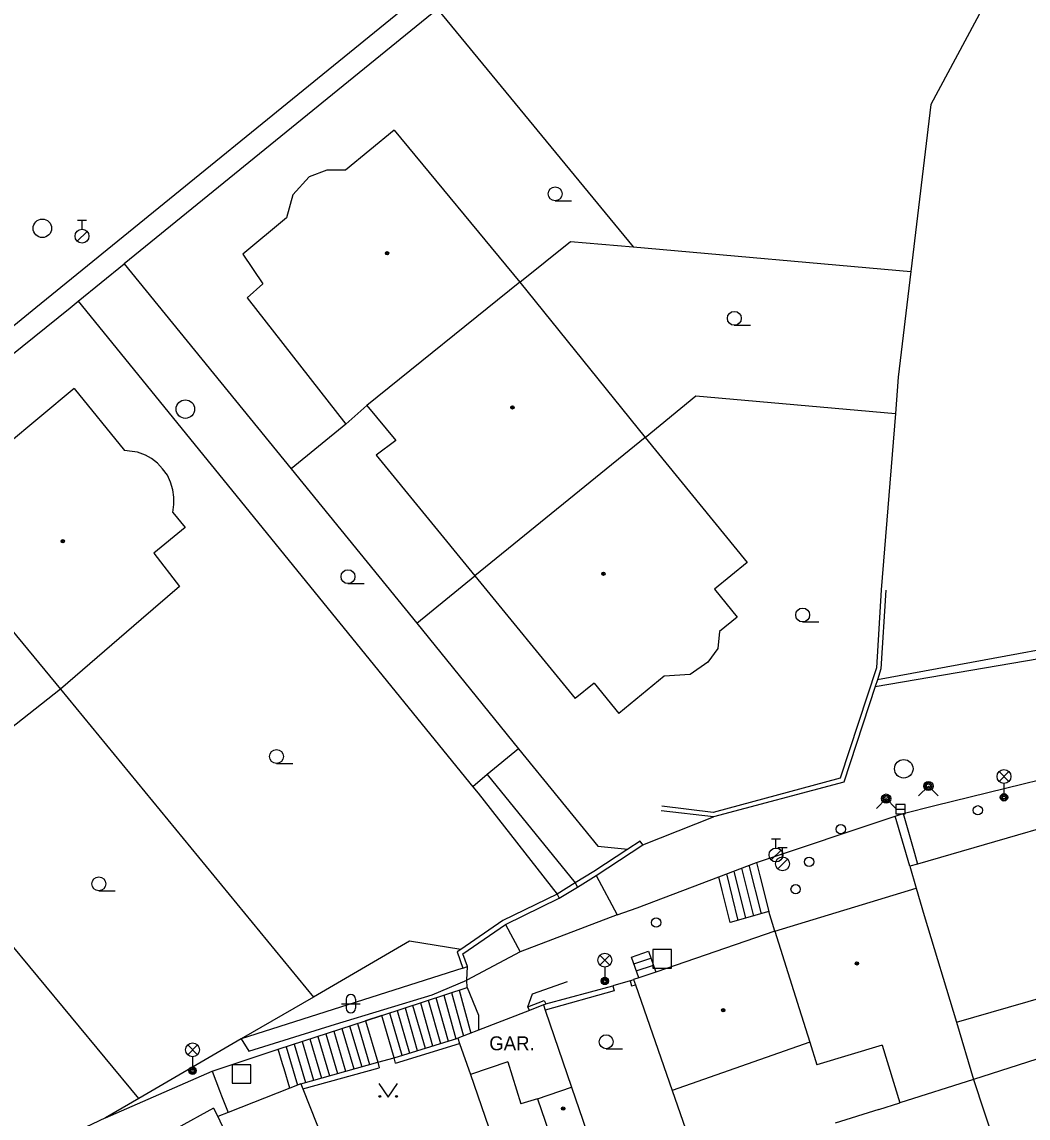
# Model space of a CAD drawing. Extents: x -598233 to -596890, y -1157848 to -1156431.
# Drawn here: x -597251.6 to -597197.2, y -1157432.7 to -1157373.5 of the extents above; entities that cross this region are included whole.
import ezdxf

# ---------------------------------------------------------------- set-up
doc = ezdxf.new("R2010")
doc.units = 0
for name, color, linetype in [('Level 10', 7, 'Continuous'), ('Level 11', 7, 'Continuous'), ('Level 26', 7, 'Continuous'), ('Level 27', 7, 'Continuous'), ('Level 28', 7, 'Continuous'), ('Level 31', 7, 'Continuous'), ('Level 33', 7, 'Continuous'), ('Level 36', 7, 'Continuous'), ('Level 39', 7, 'Continuous'), ('Level 41', 7, 'Continuous'), ('Level 5', 7, 'Continuous'), ('Level 7', 7, 'Continuous'), ('Level 8', 7, 'Continuous'), ('Level 9', 7, 'Continuous')]:
    doc.layers.add(name, color=color, linetype=linetype)

msp = doc.modelspace()

# ---------------------------------------------------------------- linework, layer by layer
at = {"layer": 'Level 10'}
for points in [[(-597250.82, -1157388.95), (-597229.74, -1157371.81)], [(-597253.2199, -1157390.9), (-597250.82, -1157388.95)], [(-597205.5, -1157409.4), (-597174.4099, -1157404.1), (-597163.67, -1157401.73), (-597154.26, -1157399.59), (-597141.84, -1157396.29)], [(-597204, -1157416.26), (-597202.29, -1157415.83), (-597191.86, -1157413.27)], [(-597211.9099, -1157418.9), (-597204.43, -1157416.4)], [(-597213.95, -1157419.68), (-597211.9099, -1157418.9)], [(-597220.57, -1157419.61), (-597219.44, -1157421.74)], [(-597219.44, -1157421.74), (-597218.35, -1157421.36), (-597213.95, -1157419.68)]]:
    msp.add_lwpolyline(points, dxfattribs=at)
at = {"layer": 'Level 11'}
for points in [[(-597229.14, -1157372.85), (-597246.05, -1157386.6)], [(-597229.14, -1157372.85), (-597218.57, -1157385.69)], [(-597224.69, -1157387.59), (-597221.95, -1157385.39), (-597218.57, -1157385.69)], [(-597218.57, -1157385.69), (-597203.57, -1157387.01)], [(-597248.53, -1157388.62), (-597246.05, -1157386.6)], [(-597246.05, -1157386.6), (-597237.04, -1157397.6599)], [(-597256.03, -1157394.64), (-597248.97, -1157388.97), (-597248.53, -1157388.62)], [(-597248.53, -1157388.62), (-597227.22, -1157414.82), (-597226.94, -1157415.17)], [(-597217.92, -1157395.9699), (-597215.18, -1157393.73), (-597204.4, -1157394.67)], [(-597234.09, -1157395.25), (-597237.04, -1157397.6599)], [(-597237.04, -1157397.6599), (-597230.26, -1157406)], [(-597230.26, -1157406), (-597227.12, -1157403.44)], [(-597230.26, -1157406), (-597224.76, -1157412.77), (-597220.48, -1157418.03), (-597218.86, -1157418.19)], [(-597249.5, -1157409.56), (-597235.83, -1157426.17)], [(-597224.76, -1157412.77), (-597226.45, -1157414.16), (-597227.22, -1157414.82)], [(-597226.45, -1157414.16), (-597221.7, -1157420.01), (-597221.57, -1157420.23)], [(-597226.94, -1157415.17), (-597222.68, -1157420.61)], [(-597245.26, -1157431.64), (-597258.01, -1157416.28)], [(-597204.43, -1157416.4), (-597204, -1157416.26)], [(-597203.64, -1157419.11), (-597204.43, -1157416.4)], [(-597204, -1157416.26), (-597203.38, -1157418.4), (-597203.21, -1157418.99)], [(-597213.13, -1157419.37), (-597212.5, -1157421.9099)], [(-597212.73, -1157419.21), (-597212.08, -1157421.8)], [(-597212.32, -1157419.06), (-597211.6599, -1157421.68)], [(-597211.9099, -1157418.9), (-597211.73, -1157419.62), (-597211.24, -1157421.56)], [(-597211.24, -1157421.56), (-597213.34, -1157422.15), (-597213.76, -1157420.42), (-597213.95, -1157419.68)], [(-597213.54, -1157419.52), (-597212.92, -1157422.03)], [(-597222.68, -1157420.61), (-597222.56, -1157420.83)], [(-597210.92, -1157422.61), (-597203.29, -1157420.3)], [(-597219.44, -1157421.74), (-597224.68, -1157423.73)], [(-597210.92, -1157422.61), (-597211.24, -1157421.56)], [(-597225.4699, -1157422.26), (-597224.68, -1157423.73)], [(-597224.68, -1157423.73), (-597227.56, -1157425.25)], [(-597218.27, -1157425.13), (-597218.6599, -1157424.01), (-597217.74, -1157423.69), (-597217.35, -1157424.82)], [(-597218.53, -1157424.38), (-597217.61, -1157424.07)], [(-597227.76, -1157424.61), (-597239.73, -1157428.43)], [(-597227.56, -1157425.25), (-597227.52, -1157424.52)], [(-597218.4, -1157424.76), (-597217.48, -1157424.44)], [(-597234.64, -1157427.64), (-597229.43, -1157426.04), (-597227.56, -1157425.25)], [(-597227.54, -1157425.65), (-597227.56, -1157425.25)], [(-597224.25, -1157426.69), (-597224, -1157425.99), (-597222.12, -1157425.33)], [(-597232.15, -1157427.1599), (-597227.54, -1157425.65)], [(-597228.38, -1157425.92), (-597227.74, -1157428.28)], [(-597227.96, -1157425.79), (-597227.33, -1157428.12)], [(-597227.54, -1157425.65), (-597226.93, -1157427.15), (-597226.92, -1157427.96)], [(-597230.06, -1157426.48), (-597229.4, -1157428.81)], [(-597229.64, -1157426.34), (-597228.98, -1157428.68)], [(-597229.2199, -1157426.2), (-597228.56, -1157428.55)], [(-597228.8, -1157426.06), (-597228.15, -1157428.43)], [(-597224.25, -1157426.69), (-597223.37, -1157426.35), (-597223.29, -1157426.54)], [(-597231.73, -1157427.02), (-597231.06, -1157429.31)], [(-597231.31, -1157426.89), (-597230.65, -1157429.19)], [(-597230.89, -1157426.75), (-597230.23, -1157429.06)], [(-597230.48, -1157426.61), (-597229.81, -1157428.93)], [(-597224.17, -1157426.89), (-597224.25, -1157426.69)], [(-597239.73, -1157428.43), (-597239.32, -1157429.08), (-597234.64, -1157427.64)], [(-597237.73, -1157428.99), (-597233.02, -1157427.45)], [(-597233.88, -1157427.73), (-597233.23, -1157429.93)], [(-597233.45, -1157427.59), (-597232.8, -1157429.81)], [(-597233.02, -1157427.45), (-597232.15, -1157427.1599)], [(-597233.02, -1157427.45), (-597232.36, -1157429.69)], [(-597231.48, -1157429.44), (-597232.15, -1157427.1599)], [(-597235.59, -1157428.29), (-597234.96, -1157430.42)], [(-597235.1599, -1157428.15), (-597234.53, -1157430.3)], [(-597234.73, -1157428.01), (-597234.1, -1157430.17)], [(-597234.3, -1157427.87), (-597233.6599, -1157430.05)], [(-597237.3, -1157428.85), (-597236.69, -1157430.92)], [(-597236.87, -1157428.71), (-597236.26, -1157430.78)], [(-597236.44, -1157428.57), (-597235.83, -1157430.6599)], [(-597236.02, -1157428.43), (-597235.4, -1157430.54)], [(-597209.04, -1157428.61), (-597216.47, -1157431.22)], [(-597241.31, -1157430.17), (-597237.73, -1157428.99)], [(-597237.11, -1157431.09), (-597237.42, -1157430.04), (-597237.5, -1157429.77), (-597237.73, -1157428.99)], [(-597232.36, -1157429.69), (-597231.48, -1157429.44)], [(-597196.32, -1157429.38), (-597200.19, -1157430.62)], [(-597247.06, -1157432.68), (-597241.31, -1157430.17)], [(-597241.31, -1157430.17), (-597240.9, -1157431.21), (-597240.79, -1157431.5), (-597240.44, -1157432.39)], [(-597227.36, -1157430.34), (-597226.38, -1157433.18)], [(-597200.19, -1157430.62), (-597198.51, -1157435.75)], [(-597223.73, -1157431.66), (-597221.9, -1157431.03)], [(-597216.47, -1157431.22), (-597215.05, -1157435.3)], [(-597205.3, -1157432.23), (-597204.17, -1157431.87)], [(-597205.3, -1157432.23), (-597207.67, -1157432.98)]]:
    msp.add_lwpolyline(points, dxfattribs=at)
at = {"layer": 'Level 26'}
for points in [[(-597217.51, -1157424.61), (-597216.51, -1157424.61), (-597216.51, -1157423.61), (-597217.51, -1157423.61)], [(-597240.2199, -1157430.82), (-597239.2199, -1157430.82), (-597239.2199, -1157429.82), (-597240.2199, -1157429.82)]]:
    msp.add_lwpolyline(points, close=True, dxfattribs=at)
at = {"layer": 'Level 27'}
msp.add_line((-597204.39, -1157416.03), (-597203.89, -1157416.03), dxfattribs=at)
msp.add_lwpolyline([(-597204.39, -1157416.28), (-597203.89, -1157416.28), (-597203.89, -1157415.78), (-597204.39, -1157415.78)], close=True, dxfattribs=at)
for centre in [(-597250.4699, -1157384.68), (-597242.75, -1157394.44), (-597203.96, -1157413.85)]:
    msp.add_circle(centre, 0.5, dxfattribs=at)
at = {"layer": 'Level 28'}
for p, q in [((-597248.58, -1157384.235), (-597248.08, -1157384.235)), ((-597248.33, -1157384.735), (-597248.33, -1157384.235)), ((-597248.588, -1157385.382), (-597248.058, -1157384.852)), ((-597211.11, -1157417.625), (-597210.61, -1157417.625)), ((-597210.86, -1157418.125), (-597210.86, -1157417.625)), ((-597211.118, -1157418.772), (-597210.588, -1157418.242)), ((-597210.76, -1157418.105), (-597210.26, -1157418.105)), ((-597210.51, -1157418.605), (-597210.51, -1157418.105)), ((-597210.768, -1157419.252), (-597210.238, -1157418.722))]:
    msp.add_line(p, q, dxfattribs=at)
for centre, radius in [((-597248.33, -1157385.11), 0.375), ((-597199.96, -1157416.09), 0.25), ((-597210.86, -1157418.5), 0.375), ((-597210.51, -1157418.98), 0.375), ((-597209.07, -1157418.87), 0.25), ((-597209.8, -1157420.35), 0.25), ((-597217.33, -1157422.15), 0.25)]:
    msp.add_circle(centre, radius, dxfattribs=at)
at = {"layer": 'Level 31'}
for points in [[(-597203.16, -1157415.31), (-597202.63, -1157414.78), (-597202.1, -1157415.31)], [(-597205.4399, -1157415.99), (-597204.9099, -1157415.46), (-597204.3799, -1157415.99)]]:
    msp.add_lwpolyline(points, dxfattribs=at)
for centre, radius in [((-597202.63, -1157414.78), 0.25), ((-597202.63, -1157414.78), 0.18), ((-597202.63, -1157414.78), 0.11), ((-597204.9099, -1157415.46), 0.25), ((-597204.9099, -1157415.46), 0.18), ((-597204.9099, -1157415.46), 0.11), ((-597207.36, -1157417.11), 0.25)]:
    msp.add_circle(centre, radius, dxfattribs=at)
at = {"layer": 'Level 33'}
for p, q in [((-597198.815, -1157414.53), (-597198.285, -1157414)), ((-597198.815, -1157414), (-597198.285, -1157414.53)), ((-597198.55, -1157414.64), (-597198.55, -1157415.39)), ((-597220.365, -1157424.44), (-597219.835, -1157423.91)), ((-597220.365, -1157423.91), (-597219.835, -1157424.44)), ((-597220.1, -1157424.55), (-597220.1, -1157425.3)), ((-597242.625, -1157429.28), (-597242.095, -1157428.75)), ((-597242.625, -1157428.75), (-597242.095, -1157429.28)), ((-597242.36, -1157429.39), (-597242.36, -1157430.14))]:
    msp.add_line(p, q, dxfattribs=at)
for centre, radius in [((-597198.55, -1157414.265), 0.375), ((-597198.55, -1157415.39), 0.2), ((-597198.55, -1157415.39), 0.1445), ((-597198.55, -1157415.39), 0.0876), ((-597220.1, -1157424.175), 0.375), ((-597220.1, -1157425.3), 0.2), ((-597220.1, -1157425.3), 0.1445), ((-597220.1, -1157425.3), 0.0876), ((-597242.36, -1157429.015), 0.375), ((-597242.36, -1157430.14), 0.2), ((-597242.36, -1157430.14), 0.1445), ((-597242.36, -1157430.14), 0.0876)]:
    msp.add_circle(centre, radius, dxfattribs=at)
at = {"layer": 'Level 36'}
for p, q in [((-597222.78, -1157383.195), (-597221.905, -1157383.195)), ((-597213.11, -1157389.915), (-597212.235, -1157389.915)), ((-597233.9699, -1157403.855), (-597233.0949, -1157403.855)), ((-597209.42, -1157405.925), (-597208.545, -1157405.925)), ((-597237.83, -1157413.565), (-597236.955, -1157413.565)), ((-597247.42, -1157420.435), (-597246.545, -1157420.435)), ((-597234.316, -1157426.526), (-597233.316, -1157426.526)), ((-597234.066, -1157426.276), (-597234.066, -1157426.776)), ((-597233.566, -1157426.276), (-597233.566, -1157426.776)), ((-597220.03, -1157428.955), (-597219.155, -1157428.955))]:
    msp.add_line(p, q, dxfattribs=at)
msp.add_lwpolyline([(-597232.3, -1157430.83), (-597231.8, -1157431.58), (-597231.3, -1157430.83)], dxfattribs=at)
for centre, radius in [((-597222.7801, -1157382.8199), 0.375), ((-597213.1101, -1157389.5399), 0.375), ((-597233.97, -1157403.4799), 0.375), ((-597209.4201, -1157405.5499), 0.375), ((-597237.8301, -1157413.1899), 0.375), ((-597247.4201, -1157420.0599), 0.375), ((-597220.0301, -1157428.5799), 0.375), ((-597232.2502, -1157431.5298), 0.05), ((-597231.3508, -1157431.5298), 0.05)]:
    msp.add_circle(centre, radius, dxfattribs=at)
for centre, start, end in [((-597233.8157, -1157426.2763), 0, 180), ((-597233.8157, -1157426.7763), 180, 0)]:
    msp.add_arc(centre, 0.25, start, end, dxfattribs=at)
at = {"layer": 'Level 39'}
for centre, radius in [((-597231.86, -1157386.03), 0.09), ((-597231.86, -1157386.03), 0.0398), ((-597225.09, -1157394.35), 0.09), ((-597225.09, -1157394.35), 0.0398), ((-597249.37, -1157401.57), 0.09), ((-597249.37, -1157401.57), 0.0398), ((-597220.18, -1157403.32), 0.09), ((-597220.18, -1157403.32), 0.0398), ((-597206.49, -1157424.35), 0.09), ((-597206.49, -1157424.35), 0.0398), ((-597213.71, -1157426.88), 0.09), ((-597213.71, -1157426.88), 0.0398), ((-597222.35, -1157432.19), 0.09), ((-597222.35, -1157432.19), 0.0398)]:
    msp.add_circle(centre, radius, dxfattribs=at)
at = {"layer": 'Level 5'}
for points in [[(-597231.48, -1157379.39), (-597234.11, -1157381.55)], [(-597231.48, -1157379.39), (-597224.69, -1157387.59)], [(-597235.12, -1157381.55), (-597236.07, -1157381.9099)], [(-597234.11, -1157381.55), (-597235.12, -1157381.55)], [(-597236.07, -1157381.9099), (-597236.95, -1157382.87)], [(-597236.95, -1157382.87), (-597237.29, -1157384.12)], [(-597237.29, -1157384.12), (-597239.64, -1157386.07)], [(-597239.64, -1157386.07), (-597238.57, -1157387.67)], [(-597238.57, -1157387.67), (-597239.42, -1157388.43)], [(-597224.69, -1157387.59), (-597232.95, -1157394.24)], [(-597224.69, -1157387.59), (-597217.92, -1157395.9699)], [(-597239.42, -1157388.43), (-597234.09, -1157395.25)], [(-597248.76, -1157393.33), (-597254.3257, -1157397.9592), (-597256.2459, -1157399.5563), (-597257.14, -1157400.3)], [(-597248.76, -1157393.33), (-597246.03, -1157396.68)], [(-597232.95, -1157394.24), (-597234.09, -1157395.25)], [(-597232.95, -1157394.24), (-597231.38, -1157396.14)], [(-597231.38, -1157396.14), (-597232.45, -1157396.93)], [(-597217.92, -1157395.9699), (-597227.12, -1157403.44)], [(-597217.92, -1157395.9699), (-597212.42, -1157402.7199)], [(-597243.43, -1157400.02), (-597243.37, -1157399.59), (-597243.37, -1157399.19), (-597243.43, -1157398.79), (-597243.56, -1157398.38), (-597243.72, -1157398.01), (-597243.98, -1157397.66), (-597244.25, -1157397.36), (-597244.58, -1157397.11), (-597244.91, -1157396.93), (-597245.19, -1157396.82), (-597245.34, -1157396.77), (-597245.63, -1157396.72), (-597246.03, -1157396.68)], [(-597232.45, -1157396.93), (-597227.12, -1157403.44)], [(-597257.14, -1157400.3), (-597249.5, -1157409.56)], [(-597243.43, -1157400.02), (-597242.76, -1157400.83)], [(-597242.76, -1157400.83), (-597244.45, -1157402.2199)], [(-597244.45, -1157402.2199), (-597243.07, -1157404.01)], [(-597212.42, -1157402.7199), (-597214.18, -1157404.1599)], [(-597227.12, -1157403.44), (-597221.7, -1157410.05)], [(-597243.07, -1157404.01), (-597245.14, -1157405.79), (-597249.5, -1157409.56)], [(-597214.18, -1157404.1599), (-597212.96, -1157405.6599)], [(-597212.96, -1157405.6599), (-597213.9099, -1157406.44)], [(-597213.9099, -1157406.44), (-597214, -1157407.35)], [(-597214, -1157407.35), (-597214.54, -1157408.1)], [(-597214.54, -1157408.1), (-597215.5, -1157408.76)], [(-597215.5, -1157408.76), (-597216.89, -1157408.86)], [(-597220.68, -1157409.23), (-597221.7, -1157410.05)], [(-597220.68, -1157409.23), (-597219.35, -1157410.87)], [(-597216.89, -1157408.86), (-597219.35, -1157410.87)], [(-597249.5, -1157409.56), (-597256.26, -1157414.87)], [(-597191.18, -1157415.51), (-597203.21, -1157418.99)], [(-597203.21, -1157418.99), (-597203.64, -1157419.11)], [(-597203.64, -1157419.11), (-597203.29, -1157420.3), (-597202.85, -1157421.76)], [(-597202.85, -1157421.76), (-597201.11, -1157427.53)], [(-597210.92, -1157422.61), (-597217.35, -1157424.82)], [(-597210.92, -1157422.61), (-597210.4099, -1157424.2199)], [(-597201.11, -1157427.53), (-597188.69, -1157423.94)], [(-597210.4099, -1157424.2199), (-597209.61, -1157426.78)], [(-597218.27, -1157425.13), (-597218.55, -1157425.23)], [(-597218.55, -1157425.23), (-597218.45, -1157425.51)], [(-597217.35, -1157424.82), (-597218.27, -1157425.13)], [(-597218.45, -1157425.51), (-597216.47, -1157431.22)], [(-597224.17, -1157426.89), (-597226.92, -1157427.96)], [(-597223.42, -1157426.59), (-597224.17, -1157426.89)], [(-597223.42, -1157426.59), (-597223.32, -1157426.88)], [(-597223.32, -1157426.88), (-597221.9, -1157431.03), (-597219.45, -1157438.16)], [(-597209.61, -1157426.78), (-597209.04, -1157428.61), (-597208.6599, -1157429.83)], [(-597201.11, -1157427.53), (-597200.19, -1157430.62)], [(-597226.92, -1157427.96), (-597228.03, -1157428.39)], [(-597228.03, -1157428.39), (-597227.94, -1157428.68)], [(-597227.94, -1157428.68), (-597227.36, -1157430.34)], [(-597205.12, -1157428.76), (-597208.6599, -1157429.83)], [(-597205.12, -1157428.76), (-597204.17, -1157431.87)], [(-597225.33, -1157429.6599), (-597227.36, -1157430.34)], [(-597225.33, -1157429.6599), (-597224.63, -1157431.94)], [(-597200.19, -1157430.62), (-597204.17, -1157431.87)], [(-597237.11, -1157431.09), (-597240.44, -1157432.39)], [(-597236.51, -1157430.85), (-597237.11, -1157431.09)], [(-597236.51, -1157430.85), (-597236.4, -1157431.13)], [(-597236.4, -1157431.13), (-597234.9, -1157434.94)], [(-597223.73, -1157431.6599), (-597224.63, -1157431.94)], [(-597223.73, -1157431.6599), (-597221.29, -1157438.78)], [(-597241.23, -1157432.17), (-597245.1599, -1157434.32)], [(-597241.23, -1157432.17), (-597240.99, -1157432.61)], [(-597240.44, -1157432.39), (-597240.99, -1157432.61)], [(-597240.99, -1157432.61), (-597239.27, -1157436.33)]]:
    msp.add_lwpolyline(points, dxfattribs=at)
at = {"layer": 'Level 7'}
for points in [[(-597199.2199, -1157371.88), (-597202.49, -1157378)], [(-597202.49, -1157378), (-597203.57, -1157387.01)], [(-597203.57, -1157387.01), (-597204.27, -1157392.7199), (-597204.4, -1157394.67)], [(-597204.4, -1157394.67), (-597205.18, -1157404.2), (-597205.44, -1157408.4099)], [(-597204.93, -1157404.21), (-597205.19, -1157408.46), (-597205.38, -1157409.05)], [(-597188.99, -1157406.03), (-597205.38, -1157409.05)], [(-597205.44, -1157408.4099), (-597207.39, -1157414.36), (-597214.26, -1157416.2), (-597217.03, -1157415.86)], [(-597205.5, -1157409.4), (-597207.19, -1157414.57), (-597214.24, -1157416.45)], [(-597205.38, -1157409.05), (-597205.5, -1157409.4)], [(-597214.24, -1157416.45), (-597217.06, -1157416.11)], [(-597218.86, -1157418.19), (-597220.7, -1157419.4), (-597221.7, -1157420.01), (-597222.68, -1157420.61)], [(-597220.57, -1157419.61), (-597218.05, -1157417.96)], [(-597218.19, -1157417.75), (-597218.86, -1157418.19)], [(-597218.05, -1157417.96), (-597218.19, -1157417.75)], [(-597225.47, -1157422.26), (-597222.56, -1157420.83), (-597221.57, -1157420.23), (-597220.57, -1157419.61)], [(-597222.68, -1157420.61), (-597225.6, -1157422.04), (-597227.88, -1157423.6)], [(-597227.52, -1157424.52), (-597227.77, -1157423.83), (-597225.4699, -1157422.26)], [(-597227.88, -1157423.6), (-597230.65, -1157423.1599), (-597235.83, -1157426.17)], [(-597227.88, -1157423.6), (-597228.07, -1157423.73), (-597227.76, -1157424.61)], [(-597227.76, -1157424.61), (-597227.52, -1157424.52)], [(-597218.74, -1157425.29), (-597218.55, -1157425.23)], [(-597218.74, -1157425.29), (-597218.6599, -1157425.57), (-597218.45, -1157425.51)], [(-597219.67, -1157425.56), (-597219.59, -1157425.84), (-597223.32, -1157426.88)], [(-597223.29, -1157426.54), (-597219.67, -1157425.56)], [(-597235.83, -1157426.17), (-597239.73, -1157428.43)], [(-597223.42, -1157426.59), (-597223.29, -1157426.54)], [(-597239.73, -1157428.43), (-597245.26, -1157431.64)], [(-597231.48, -1157429.44), (-597228.03, -1157428.39)], [(-597231.4, -1157429.73), (-597227.94, -1157428.68)], [(-597231.4, -1157429.73), (-597231.48, -1157429.44)], [(-597236.51, -1157430.85), (-597232.36, -1157429.69)], [(-597236.4, -1157431.13), (-597232.28, -1157429.98)], [(-597232.36, -1157429.69), (-597232.28, -1157429.98)], [(-597245.26, -1157431.64), (-597247.06, -1157432.68)], [(-597247.06, -1157432.68), (-597252.88, -1157435.44)]]:
    msp.add_lwpolyline(points, dxfattribs=at)
at = {"layer": 'Level 8'}
for points in [[(-597218.05, -1157417.96), (-597214.24, -1157416.45)], [(-597218.74, -1157425.29), (-597219.67, -1157425.56)]]:
    msp.add_lwpolyline(points, dxfattribs=at)
at = {"layer": 'Level 9'}
for points in [[(-597232.15, -1157427.1599), (-597227.54, -1157425.65)], [(-597237.73, -1157428.99), (-597233.02, -1157427.45)], [(-597232.15, -1157427.1599), (-597233.02, -1157427.45)]]:
    msp.add_lwpolyline(points, dxfattribs=at)

# ---------------------------------------------------------------- texts
at = {"layer": 'Level 41'}
msp.add_text('GAR.', height=0.75, dxfattribs=at).set_placement((-597226.34, -1157429.04))

doc.saveas('drawing.dxf')
